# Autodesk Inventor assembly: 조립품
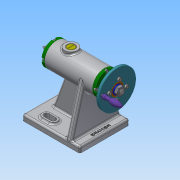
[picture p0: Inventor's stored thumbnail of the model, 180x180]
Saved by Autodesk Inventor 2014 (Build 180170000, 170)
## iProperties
Created: 2019-10
Part Number: 조립품
Document SubType Name: Assembly
Designer: net
Author: net
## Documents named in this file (18)
- C:\Users\net\Desktop\491004V1038\조립품.iam
- C:\Users\net\Desktop\491004V1038\본체.ipt
- C:\Users\net\Desktop\491004V1038\센터.ipt
- C:\Users\net\Desktop\491004V1038\센터홀더.ipt
- C:\Users\net\Desktop\491004V1038\중공축.ipt
- C:\Users\net\Desktop\491004V1038\슬리브.ipt
- C:\Users\net\Desktop\491004V1038\나사.ipt
- C:\Users\net\Desktop\491004V1038\볼트 M3.ipt
- C:\Users\net\Desktop\491004V1038\부시.ipt
- C:\Users\net\Desktop\491004V1038\커버.ipt
- C:\Users\net\Desktop\491004V1038\나사축.ipt
- C:\Users\net\Desktop\491004V1038\키 4 x 4 x 10.ipt
- C:\Users\net\Desktop\491004V1038\플랜지.ipt
- C:\Users\net\Desktop\491004V1038\돌림판.ipt
- C:\Users\net\Desktop\491004V1038\와셔.ipt
- C:\Users\net\Desktop\491004V1038\너트 M8.ipt
- C:\Users\net\Desktop\491004V1038\핸들.ipt
- C:\Users\net\Desktop\491004V1038\멈춤나사 M3.ipt
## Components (2 placed, 2 different names)
1. 플랜지:1
2. 핸들:1
